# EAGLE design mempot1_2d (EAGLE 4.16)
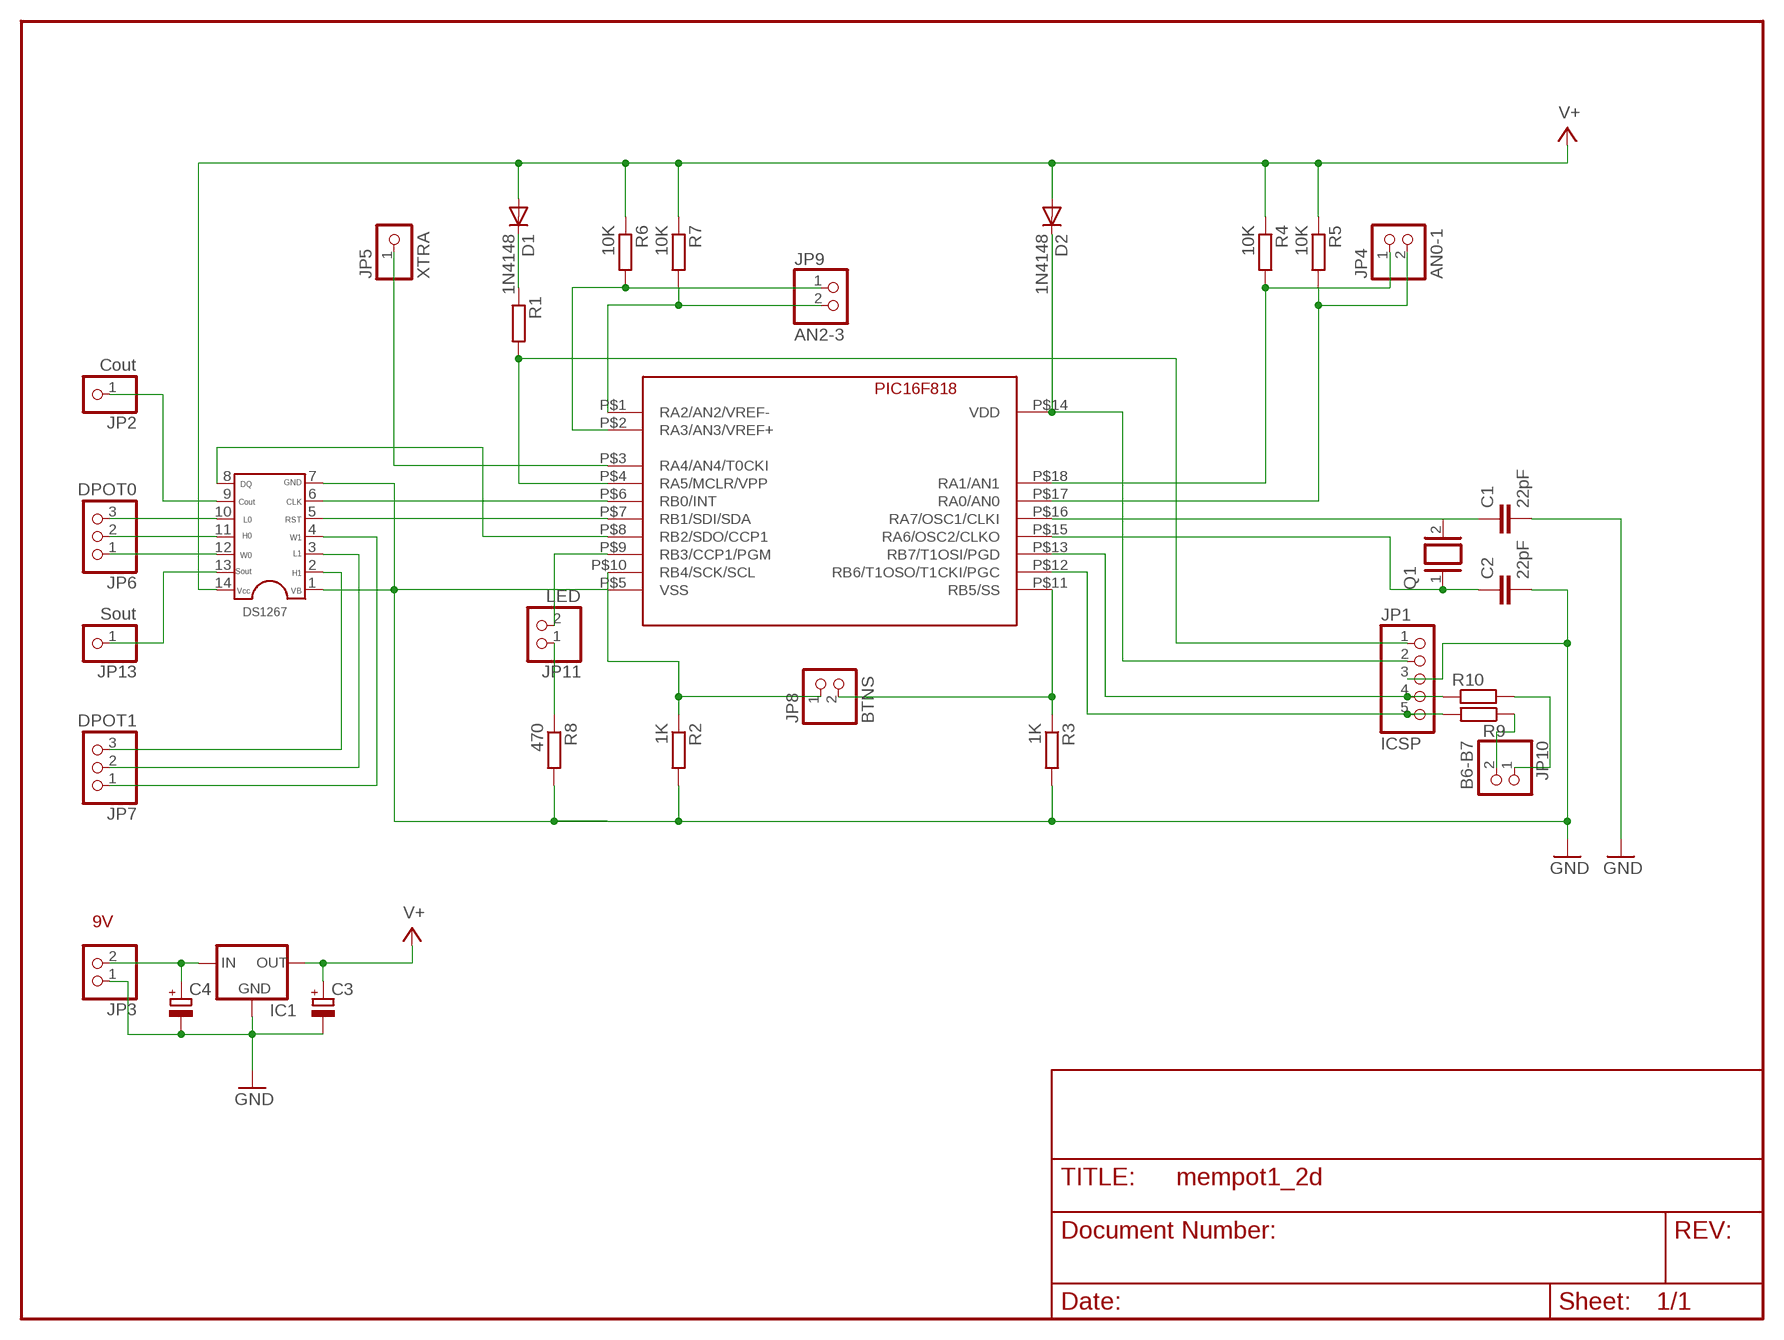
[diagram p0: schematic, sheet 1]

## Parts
C1  22pF  C2,5-3  [C2.5-3]
C2  22pF  C2,5-3  [C2.5-3]
C3  CPOL-EUTT2D5  [TT2D5]
C4  CPOL-EUTT2D5  [TT2D5]
D1  1N4148  [DO35-10]
D2  1N4148  [DO35-10]
IC1  78LXX  [78LXX]
JP1  ICSP  PINHD-1X5  [1X05]
JP2  Cout  PINHD-1X1  [1X01]
JP3  PINHD-1X2  [1X02]
JP4  AN0-1  PINHD-1X2  [1X02]
JP5  XTRA  PINHD-1X1  [1X01]
JP6  DPOT0  PINHD-1X3  [1X03]
JP7  DPOT1  PINHD-1X3  [1X03]
JP8  BTNS  PINHD-1X2  [1X02]
JP9  AN2-3  PINHD-1X2  [1X02]
JP10  B6-B7  PINHD-1X2  [1X02]
JP11  LED  PINHD-1X2  [1X02]
JP13  Sout  PINHD-1X1  [1X01]
PIC1  PIC16F818  [PIC16F818]
Q1  XTAL/S  [QS]
R1  R-EU_0204/5  [0204/5]
R2  1K  R-EU_0204/5  [0204/5]
R3  1K  R-EU_0204/5  [0204/5]
R4  10K  R-EU_0204/5  [0204/5]
R5  10K  R-EU_0204/5  [0204/5]
R6  10K  R-EU_0204/5  [0204/5]
R7  10K  R-EU_0204/5  [0204/5]
R8  470  R-EU_0204/5  [0204/5]
R9  R-EU_0204/5  [0204/5]
R10  R-EU_0204/5  [0204/5]
U$1  DS1267  [DIL14]

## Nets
DPOT0: JP6.1 U$1.12(W0)
GND: C1.2 C2.2 C3.- C4.- IC1.GND JP1.3 JP3.1 PIC1.P$5(VSS) R2.2 R3.2 R8.2 U$1.1(VB) U$1.7(GND)
N$1: PIC1.P$6(RB0/INT) U$1.6(CLK)
N$2: PIC1.P$7(RB1/SDI/SDA) U$1.5(RST)
N$3: JP11.1 R8.1
N$4: JP1.1 PIC1.P$4(RA5/MCLR/VPP) R1.2
N$5: C4.+ IC1.IN JP3.2
N$6: JP10.2 R9.1
N$7: JP10.1 R10.2
N$8: JP8.2 PIC1.P$11(RB5/SS) R3.1
N$9: C2.1 PIC1.P$15(RA6/OSC2/CLKO) Q1.1
N$10: JP6.2 U$1.11(H0)
N$11: C1.1 PIC1.P$16(RA7/OSC1/CLKI) Q1.2
N$12: JP6.3 U$1.10(L0)
N$14: JP7.3 U$1.2(H1)
N$15: JP7.2 U$1.3(L1)
N$16: JP11.2 PIC1.P$9(RB3/CCP1/PGM)
N$17: JP7.1 U$1.4(W1)
N$18: PIC1.P$8(RB2/SDO/CCP1) U$1.8(DQ)
N$19: JP8.1 PIC1.P$10(RB4/SCK/SCL) R2.1
N$20: JP5.1 PIC1.P$3(RA4/AN4/T0CKI)
N$21: JP13.1 U$1.13(SOUT)
N$22: JP2.1 U$1.9(COUT)
N$23: JP4.1 PIC1.P$18(RA1/AN1) R4.2
N$24: JP4.2 PIC1.P$17(RA0/AN0) R5.2
N$25: JP9.1 PIC1.P$2(RA3/AN3/VREF+) R6.2
N$26: JP9.2 PIC1.P$1(RA2/AN2/VREF-) R7.2
N$27: JP1.5 PIC1.P$12(RB6/T1OSO/T1CKI/PGC) R9.2
N$28: D2.C JP1.2 PIC1.P$14(VDD)
N$30: D1.C R1.1
N$31: JP1.4 PIC1.P$13(RB7/T1OSI/PGD) R10.1
V+: C3.+ D1.A D2.A IC1.OUT R4.1 R5.1 R6.1 R7.1 U$1.14(VCC)

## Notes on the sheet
- 9V

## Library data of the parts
C1 C2 = capacitor-wima:C: CAPACITOR
C3 C4 = rcl:CPOL-EU: POLARIZED CAPACITOR, European symbol
D1 D2 = diode:1N4148: DIODE
IC1 = v-reg:78LXX: VOLTAGE REGULATOR
JP1 = pinhead:PINHD-1X5: PIN HEADER
JP2 JP5 JP13 = pinhead:PINHD-1X1: PIN HEADER
JP3 JP4 JP8-JP11 = pinhead:PINHD-1X2: PIN HEADER
JP6 JP7 = pinhead:PINHD-1X3: PIN HEADER
PIC1 = pic16f818:PIC16F818: Microchipp Component 16F818 Francesco Cuzzupoli virtex2@virgilio.it
Q1 = special:XTAL/S: CRYSTAL
R1-R10 = rcl:R-EU_: RESISTOR, European symbol
U$1 = DS1267:DS1267

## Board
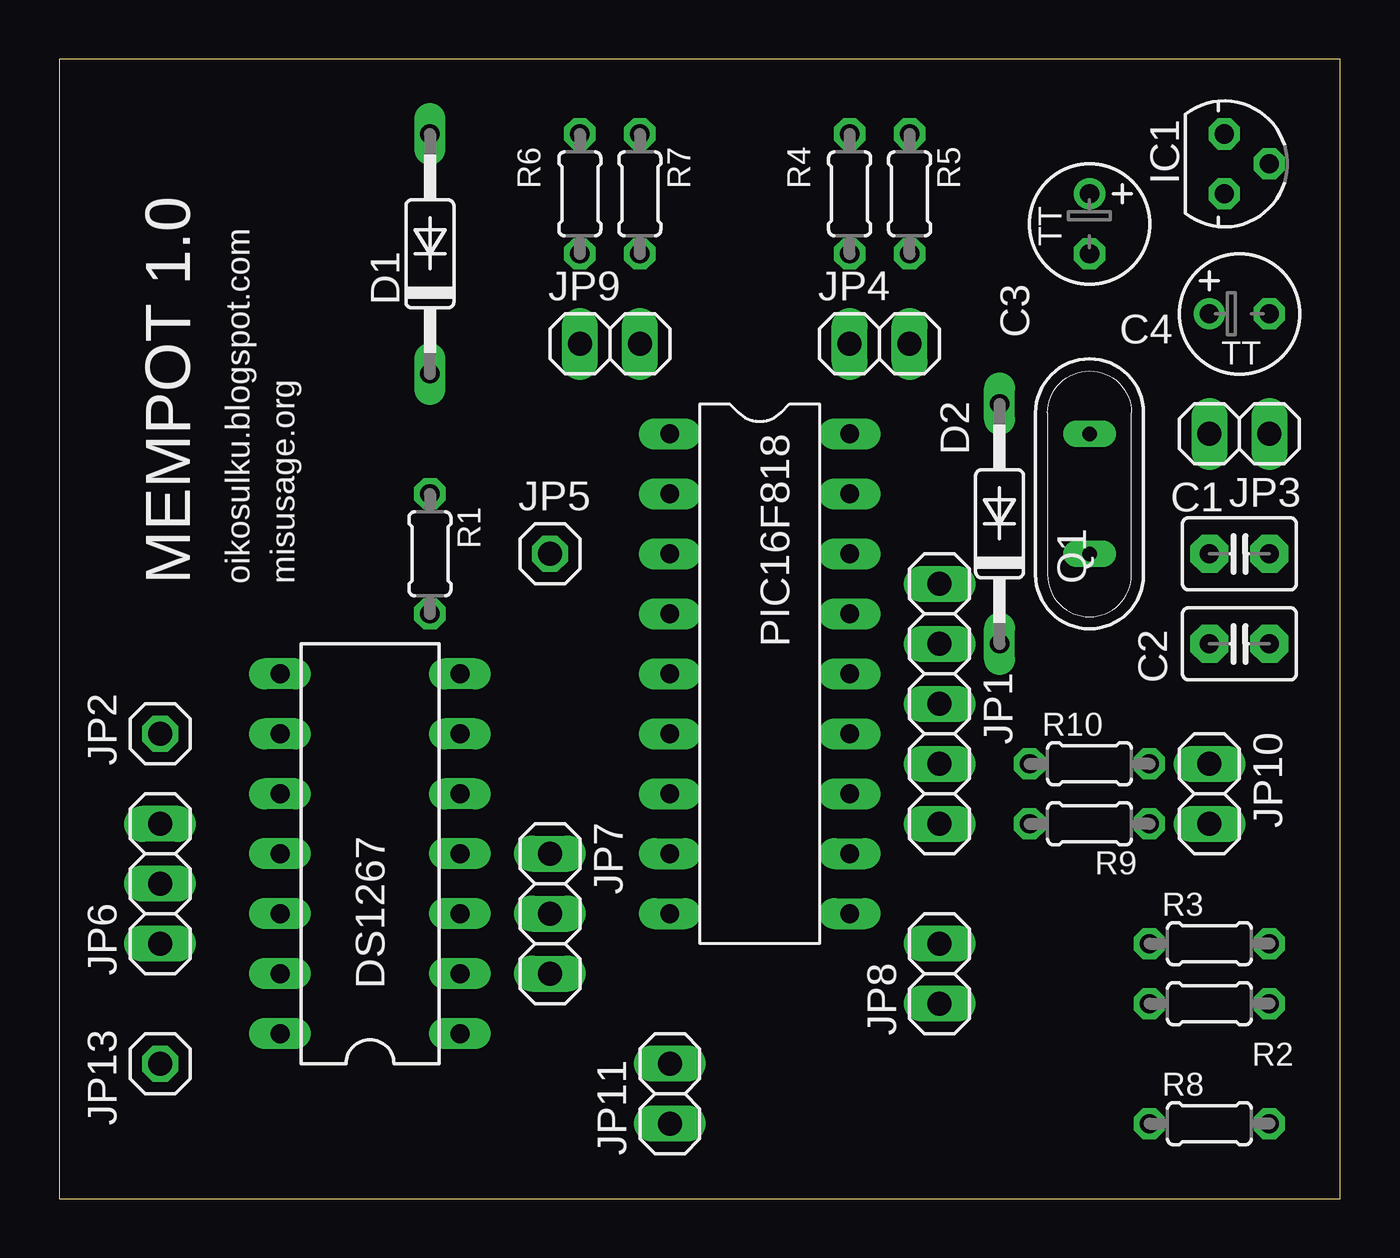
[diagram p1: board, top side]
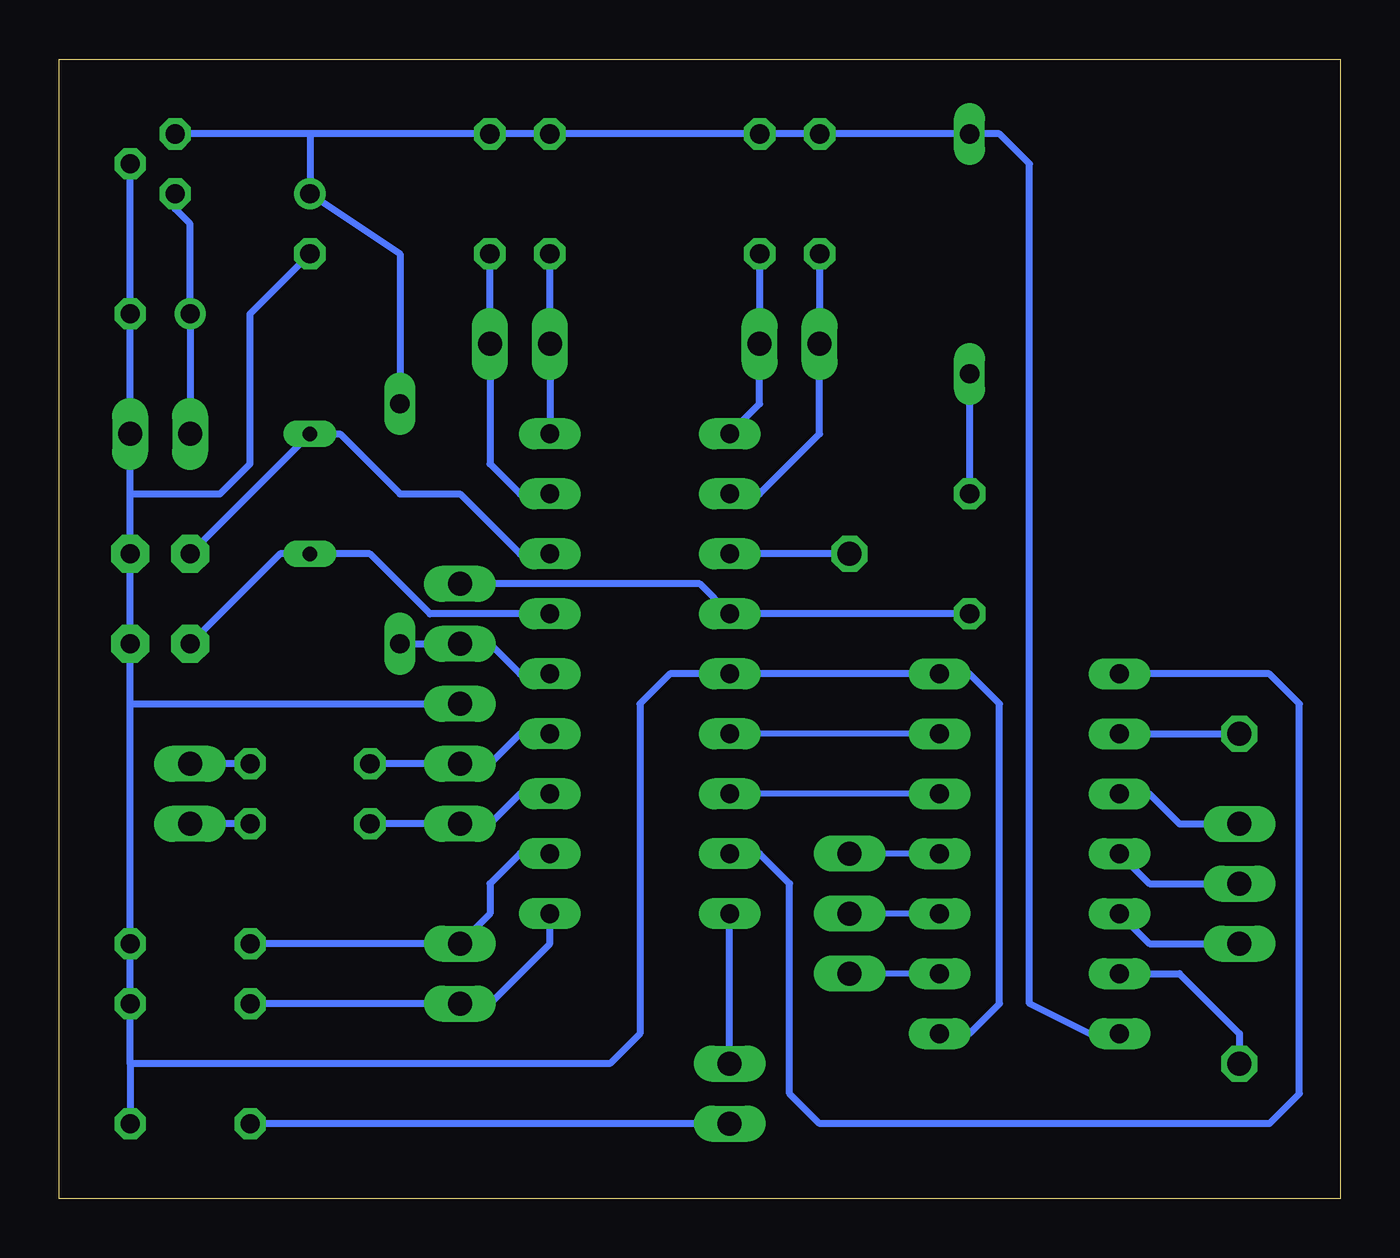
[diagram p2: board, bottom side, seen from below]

Size 54.28 x 48.25 mm. Coordinates in mm from the lower left corner, seen from the top.
Outline: 0,0 54.28,0 54.28,48.25 0,48.25 0,0
Copper layers (1*16): Top 0.035mm / dielectric 1.5mm / Bottom 0.035mm
Design rules "default": minimum track width 10mil, minimum drill 24mil, track to track 8mil, track to pad 8mil, pad to pad 8mil, via to via 8mil, smd to smd 8mil, copper to edge 40mil, drill to drill 8mil, minimum pad ring 10mil, minimum via ring 8mil, stop-mask expansion 4mil, vias tented up to drill 0mil, thermal gap 10mil

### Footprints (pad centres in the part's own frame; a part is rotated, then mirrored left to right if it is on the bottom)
C2.5-3 = drill 0.813 pad 1.6 octagon: 1 -1.27,0; 2 1.27,0
TT2D5 = drill 0.813 round: + -1.27,0 | drill 0.813 octagon: - 1.27,0
DO35-10 = drill 0.813 long: A 5.08,0; C -5.08,0
78LXX = drill 0.813 octagon: GND 0,1.905; IN 1.27,0; OUT -1.27,0
1X05 = drill 1.016 long: 1 -5.08,0; 2 -2.54,0; 3 0,0; 4 2.54,0; 5 5.08,0
1X01 = drill 1.016 octagon: 1 0,0
1X02 = drill 1.016 long: 1 -1.27,0; 2 1.27,0
1X03 = drill 1.016 long: 1 -2.54,0; 2 0,0; 3 2.54,0
PIC16F818 = drill 0.8 long: P$1 -8.89,-3.81; P$2 -6.35,-3.81; P$3 -3.81,-3.81; P$4 -1.27,-3.81; P$5 1.27,-3.81; P$6 3.81,-3.81; P$7 6.35,-3.81; P$8 8.89,-3.81; P$9 11.43,-3.81; P$10 11.43,3.81; P$11 8.89,3.81; P$12 6.35,3.81; P$13 3.81,3.81; P$14 1.27,3.81; P$15 -1.27,3.81; P$16 -3.81,3.81; P$17 -6.35,3.81; P$18 -8.89,3.81
QS = drill 0.61 long: 1 -2.54,0; 2 2.54,0
0204/5 = drill 0.813 octagon: 1 -2.54,0; 2 2.54,0
DIL14 = drill 0.8 long: 1 -7.62,-3.81; 2 -5.08,-3.81; 3 -2.54,-3.81; 4 0,-3.81; 5 2.54,-3.81; 6 5.08,-3.81; 7 7.62,-3.81; 8 7.62,3.81; 9 5.08,3.81; 10 2.54,3.81; 11 0,3.81; 12 -2.54,3.81; 13 -5.08,3.81; 14 -7.62,3.81

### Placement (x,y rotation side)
C1  50,27.3 0 top
C2  50,23.49 0 top
C3  43.65,41.27 270 top
C4  50,37.46 0 top
D1  15.71,40 90 top
D2  39.84,28.57 90 top
IC1  49.37,43.81 270 top
JP1  37.3,20.95 270 top
JP2  4.28,19.68 0 top
JP3  50,32.38 180 top
JP4  34.76,36.19 0 top
JP5  20.79,27.3 0 top
JP6  4.28,13.33 90 top
JP7  20.79,12.06 270 top
JP8  37.3,9.52 90 top
JP9  23.33,36.19 0 top
JP10  48.73,17.14 270 top
JP11  25.87,4.44 90 top
JP13  4.28,5.71 0 top
PIC1  29.68,23.49 270 top
Q1  43.65,29.84 90 top
R1  15.71,27.3 270 top
R2  48.73,8.25 0 top
R3  48.73,10.79 0 top
R4  33.49,42.54 270 top
R5  36.03,42.54 270 top
R6  22.06,42.54 270 top
R7  24.6,42.54 270 top
R8  48.73,3.17 0 top
R9  43.65,15.87 180 top
R10  43.65,18.41 0 top
U$1  13.17,14.6 90 top

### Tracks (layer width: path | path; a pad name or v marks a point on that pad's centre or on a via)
DPOT0
  Bottom 0.305: U$1.12 8.09,10.79 JP6.1
GND
  Bottom 0.305: U$1.1 15.71,6.98 14.44,8.25 14.44,20.95 15.71,22.22 U$1.7 PIC1.P$5 28.41,22.22 29.68,20.95 29.68,6.98 30.95,5.71 51.27,5.71 | 51.27,5.71 R8.2 | 51.27,5.71 R2.2 R3.2 51.27,20.95 | 51.27,20.95 C2.2 C1.2 51.27,29.84 | 51.27,20.95 JP1.3 | IC1.GND C4.- JP3.1 51.27,29.84 | 51.27,29.84 47.46,29.84 46.19,31.11 46.19,37.46 C3.-
N$1
  Bottom 0.254: U$1.6 PIC1.P$6
N$2
  Bottom 0.254: U$1.5 PIC1.P$7
N$3
  Bottom 0.305: JP11.1 R8.1
N$4
  Bottom 0.305: JP1.1 27.14,26.03 PIC1.P$4 R1.2
N$5
  Bottom 0.305: IC1.IN 49.37,41.91 48.73,41.27 C4.+ JP3.2
N$6
  Bottom 0.305: R9.1 JP10.2
N$7
  Bottom 0.305: R10.2 JP10.1
N$8
  Bottom 0.305: PIC1.P$11 34.76,14.6 36.03,13.33 36.03,12.06 JP8.2 R3.1
N$9
  Bottom 0.305: PIC1.P$15 38.57,24.76 41.11,27.3 Q1.1 44.92,27.3 C2.1
N$10
  Bottom 0.305: U$1.11 8.09,13.33 JP6.2
N$11
  Bottom 0.305: PIC1.P$16 34.76,27.3 37.3,29.84 39.84,29.84 42.38,32.38 Q1.2 C1.1
N$12
  Bottom 0.305: U$1.10 8.09,17.14 6.82,15.87 JP6.3
N$14
  Bottom 0.254: U$1.2 JP7.3
N$15
  Bottom 0.254: U$1.3 JP7.2
N$16
  Bottom 0.305: JP11.2 PIC1.P$9
N$17
  Bottom 0.254: U$1.4 JP7.1
N$18
  Bottom 0.305: PIC1.P$8 24.6,14.6 23.33,13.33 23.33,4.44 22.06,3.17 3.01,3.17 1.74,4.44 1.74,20.95 3.01,22.22 U$1.8
N$19
  Bottom 0.305: R2.1 JP8.1 36.03,8.25 33.49,10.79 PIC1.P$10
N$20
  Bottom 0.305: JP5.1 PIC1.P$3
N$21
  Bottom 0.305: U$1.13 6.82,9.52 4.28,6.98 JP13.1
N$22
  Bottom 0.305: U$1.9 JP2.1
N$23
  Bottom 0.305: R4.2 JP4.1 PIC1.P$18
N$24
  Bottom 0.305: PIC1.P$17 34.76,29.84 36.03,31.11 JP4.2 R5.2
N$25
  Bottom 0.305: PIC1.P$2 24.6,29.84 22.06,32.38 JP9.1 R6.2
N$26
  Bottom 0.305: PIC1.P$1 24.6,33.65 JP9.2 R7.2
N$27
  Bottom 0.305: PIC1.P$12 34.76,17.14 36.03,15.87 JP1.5 R9.2
N$28
  Bottom 0.305: PIC1.P$14 34.76,22.22 36.03,23.49 JP1.2 D2.C
N$30
  Bottom 0.305: D1.C R1.1
N$31
  Bottom 0.305: PIC1.P$13 34.76,19.68 36.03,18.41 JP1.4 R10.1
V+
  Bottom 0.305: U$1.14 10.63,6.98 13.17,8.25 13.17,43.81 14.44,45.08 D1.A | D1.A R6.1 R7.1 | D1.A R4.1 R5.1 43.65,45.08 | D2.A 39.84,40 C3.+ 43.65,45.08 | 43.65,45.08 IC1.OUT

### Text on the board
tPlace: MEMPOT 1.0 | oikosulku.blogspot.com | misusage.org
